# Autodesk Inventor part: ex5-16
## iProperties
Created: 2006-03
Part Number: ex5-16
Document SubType Name: Modeling
Designer: Elise Moss
Author: Elise Moss
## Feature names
1. Revolution1
2. Hole1
3. Split1
